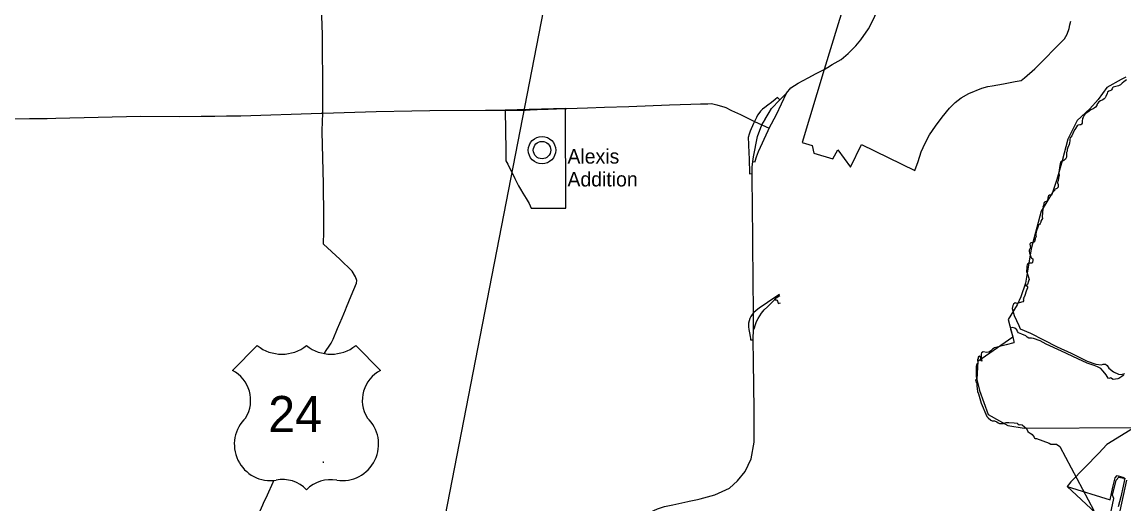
# Model space of a CAD drawing. Extents: x 0 to 750, y 0 to 507.
# Drawn here: x 327.4 to 406.4, y 302.6 to 337.1 of the extents above; entities that cross this region are included whole.
import ezdxf

# ---------------------------------------------------------------- set-up
doc = ezdxf.new("R2010")
doc.units = 0
for name, color, linetype in [('DV_X_Corp_Line', 7, 'Continuous'), ('GM_X_County', 7, 'Continuous'), ('GM_X_Interchange_Ramps', 7, 'Continuous'), ('GM_X_Interstate_Route', 7, 'Continuous'), ('GM_X_Rail_Line', 7, 'Continuous'), ('GM_X_State_Route', 7, 'Continuous'), ('GM_X_US_Route', 7, 'Continuous'), ('SH_Data', 7, 'Continuous')]:
    doc.layers.add(name, color=color, linetype=linetype)

msp = doc.modelspace()

# ---------------------------------------------------------------- linework, layer by layer
at = {"layer": 'DV_X_Corp_Line'}
for points in [[(386.603, 339.237), (385.928, 336.978), (384.925, 333.716), (383.344, 328.467), (384.054, 328.263), (384.187, 327.707), (385.543, 327.316), (385.894, 327.945), (386.801, 326.717), (387.606, 328.321), (391.432, 326.469), (391.659, 327.121), (391.872, 327.808), (392.162, 328.419), (392.468, 329.014), (392.894, 329.657), (393.381, 330.299), (393.907, 330.931), (394.304, 331.334), (394.75, 331.676), (395.285, 331.982), (396.216, 332.36), (396.668, 332.496), (396.964, 332.546), (397.77, 332.676), (398.618, 332.851), (399.058, 332.907), (399.277, 333.099), (400.018, 333.756), (402.156, 335.914), (402.357, 336.246), (402.499, 336.649), (402.548, 336.899), (402.608, 337.178)], [(406.565, 333.158), (406.225, 332.985), (405.184, 332.415), (404.569, 331.568), (403.968, 330.884), (403.068, 330.053), (402.407, 328.725), (401.978, 327.164), (401.6, 325.819), (401.287, 324.901), (400.49, 323.558), (399.763, 320.859), (399.594, 319.836), (399.361, 318.388), (399.022, 317.425), (398.755, 316.846), (398.12, 315.8), (398.447, 314.534), (395.94, 312.788), (395.871, 311.487), (396.061, 310.702), (396.672, 308.99), (398.093, 308.182), (399.258, 308.013), (407.183, 308.053), (405.205, 306.834), (404.62, 306.208), (402.601, 304.165), (402.358, 303.814), (404.38, 301.943)], [(404.38, 301.943), (402.358, 303.814), (405.428, 302.869), (405.623, 303.771), (405.781, 304.437), (405.942, 304.621), (406.416, 304.472), (406.456, 304.307), (406.368, 303.846), (406.189, 303.085), (406.015, 302.368)]]:
    msp.add_lwpolyline(points, dxfattribs=at)
msp.add_lwpolyline([(362.075, 327.909), (362.085, 327.165), (362.22, 326.918), (362.346, 326.651), (362.55, 326.243), (362.719, 325.892), (362.874, 325.597), (362.993, 325.365), (363.134, 325.14), (363.31, 324.852), (363.542, 324.459), (363.753, 324.107), (363.906, 323.769), (366.389, 323.764), (366.35, 330.91), (362.041, 330.785)], close=True, dxfattribs=at)
for radius in [0.982, 0.623]:
    msp.add_circle((364.676, 327.927), radius, dxfattribs=at)
at = {"layer": 'GM_X_County'}
for points in [[(406.615, 332.959), (406.409, 332.826), (406.293, 332.731), (406.167, 332.601), (406.035, 332.529), (405.738, 332.457), (405.65, 332.437), (405.608, 332.402), (405.583, 332.323), (405.534, 332.251), (405.478, 332.212), (405.348, 332.156), (405.253, 332.072), (405.214, 331.98), (405.128, 331.764), (405.07, 331.678), (405.003, 331.601), (404.917, 331.536), (404.745, 331.471), (404.615, 331.383), (404.539, 331.3), (404.483, 331.191), (404.465, 331.121), (404.383, 331.001), (404.288, 330.931), (404.214, 330.898), (404.045, 330.808), (403.827, 330.639), (403.646, 330.518), (403.546, 330.4), (403.514, 330.319), (403.493, 330.268), (403.46, 330.193), (403.435, 330.015), (403.418, 329.933), (403.425, 329.859), (403.388, 329.785), (403.349, 329.75), (403.256, 329.734), (403.126, 329.711), (403.07, 329.662), (402.892, 329.395), (402.804, 329.249), (402.753, 329.115), (402.676, 328.948), (402.56, 328.801), (402.532, 328.713), (402.53, 328.588), (402.523, 328.46), (402.481, 328.323), (402.4, 328.124), (402.342, 327.976), (402.344, 327.853), (402.312, 327.769), (402.305, 327.523), (402.289, 327.416), (402.233, 327.282), (402.119, 327.177), (402.006, 327.126), (401.911, 327.106), (401.863, 327.062), (401.841, 326.945), (401.808, 326.681), (401.774, 326.479), (401.746, 326.384), (401.739, 326.296), (401.769, 326.11), (401.725, 325.925), (401.699, 325.723), (401.66, 325.644), (401.651, 325.574), (401.692, 325.456), (401.713, 325.349), (401.695, 325.268), (401.611, 325.173), (401.556, 325.15), (401.479, 325.131), (401.472, 325.101), (401.484, 325.085), (401.414, 325.022), (401.312, 324.923), (401.261, 324.825), (401.245, 324.749), (401.219, 324.702), (401.191, 324.695), (401.129, 324.705), (401.089, 324.7), (401.02, 324.656), (400.992, 324.596), (400.932, 324.34), (400.876, 324.238), (400.825, 324.215), (400.76, 324.222), (400.718, 324.208), (400.702, 324.178), (400.674, 324.092), (400.646, 323.937), (400.63, 323.913), (400.609, 323.883), (400.623, 323.835), (400.628, 323.753), (400.604, 323.688), (400.588, 323.461), (400.553, 323.155), (400.581, 323.034), (400.539, 322.953), (400.465, 322.837), (400.451, 322.761), (400.403, 322.665), (400.361, 322.607), (400.328, 322.603), (400.294, 322.559), (400.243, 322.413), (400.157, 322.155), (400.134, 322.065), (400.131, 322.018), (400.092, 321.923), (400.101, 321.863), (400.106, 321.798), (400.122, 321.705), (400.099, 321.668), (400.062, 321.617), (400.041, 321.545), (400.038, 321.468), (399.997, 321.355), (399.92, 321.306), (399.832, 321.29), (399.737, 321.28), (399.707, 321.269), (399.688, 321.243), (399.681, 321.185), (399.69, 321.065), (399.723, 320.956), (399.672, 320.844), (399.621, 320.752), (399.619, 320.668), (399.649, 320.566), (399.697, 320.423), (399.772, 320.202), (399.823, 320.188), (399.876, 320.127), (399.883, 320.051), (399.853, 319.886), (399.823, 319.835), (399.667, 319.817), (399.63, 319.824), (399.579, 319.828), (399.54, 319.807), (399.496, 319.775), (399.498, 319.74), (399.503, 319.722), (399.477, 319.698), (399.456, 319.617), (399.456, 319.52), (399.435, 319.22), (399.482, 319.104), (399.57, 318.814), (399.621, 318.647), (399.567, 318.529), (399.491, 318.29), (399.465, 318.262), (399.426, 318.253), (399.387, 318.251), (399.377, 318.23), (399.389, 318.209), (399.412, 318.204), (399.47, 318.179), (399.493, 318.149), (399.498, 318.07), (399.414, 317.819), (399.301, 317.499), (399.245, 317.337), (399.196, 317.267), (399.206, 317.223), (399.208, 317.184), (399.208, 317.123), (399.157, 317.047), (398.901, 316.99), (398.769, 316.935), (398.609, 316.978), (398.502, 316.894), (398.451, 316.802), (398.407, 316.568), (398.543, 316.082), (398.879, 315.361), (398.982, 315.119), (399.708, 314.808), (400.66, 314.331), (401.623, 313.832), (402.634, 313.375), (403.793, 312.815), (404.41, 312.585), (404.806, 312.551), (404.927, 312.595), (405.092, 312.588), (405.227, 312.482), (405.333, 312.295), (405.67, 312.039), (406.021, 311.882), (406.211, 311.849), (406.321, 311.863), (406.487, 311.908)], [(406.423, 311.808), (406.2, 311.669), (406.057, 311.571), (405.984, 311.534), (405.655, 311.483), (405.589, 311.519), (405.516, 311.596), (405.439, 311.607), (405.399, 311.578), (405.344, 311.563), (405.289, 311.593), (405.146, 311.816), (404.927, 312.079), (404.755, 312.284), (404.521, 312.39), (404.287, 312.485), (403.774, 312.672), (403.116, 312.961), (401.941, 313.513), (400.84, 314.029), (400.416, 314.252), (399.944, 314.432), (399.783, 314.45), (399.596, 314.443), (399.487, 314.523), (399.373, 314.611), (399.095, 314.75), (398.861, 314.845), (398.777, 314.936), (398.733, 315.061), (398.601, 315.167), (398.411, 315.226), (398.287, 315.167), (398.283, 315.097), (398.367, 314.797), (398.422, 314.64), (398.532, 314.212), (398.524, 314.117), (397.983, 313.967), (397.14, 313.754), (397.127, 313.753), (396.992, 313.664), (396.882, 313.554), (396.732, 313.458), (396.588, 313.434), (396.333, 313.469), (396.198, 313.396), (396.187, 313.308), (396.187, 313.093), (396.205, 312.957), (396.223, 312.8), (396.187, 312.826), (396.146, 312.983), (396.106, 313.129), (396.066, 313.188), (396.048, 313.173), (395.963, 313.1), (395.956, 313.005), (395.916, 312.928), (395.916, 312.822), (395.934, 312.73), (395.916, 312.613), (395.85, 312.573), (395.824, 312.397), (395.821, 311.695), (395.854, 311.636), (395.872, 311.56), (395.832, 311.497), (395.784, 311.439), (395.795, 311.38), (395.821, 311.263), (395.868, 311.223), (395.857, 311.033), (395.916, 310.641), (395.978, 310.455), (396.179, 309.8), (396.578, 308.845), (396.67, 308.739), (396.867, 308.585), (396.973, 308.534), (397.068, 308.534), (397.145, 308.523), (397.295, 308.454), (397.405, 308.384), (397.485, 308.344), (397.591, 308.336), (397.782, 308.336), (397.837, 308.351), (397.972, 308.41), (398.17, 308.399), (398.554, 308.395), (398.751, 308.355), (398.813, 308.304), (398.905, 308.249), (399.015, 308.263), (399.128, 308.234), (399.282, 308.088), (399.424, 307.967), (399.52, 307.755), (399.655, 307.663), (399.746, 307.612), (399.845, 307.546), (399.977, 307.352), (400.013, 307.286), (400.061, 307.257), (400.149, 307.268), (401.056, 306.928), (401.184, 306.866), (401.455, 306.866), (401.572, 306.847), (401.817, 306.686), (404.25, 302.102)], [(405.311, 301.169), (405.684, 302.955), (405.589, 303.196), (405.86, 304.279), (406.043, 304.499), (406.526, 304.389)], [(406.599, 304.279), (406.006, 301.535), (406.123, 301.36), (406.474, 301.286)]]:
    msp.add_lwpolyline(points, dxfattribs=at)
at = {"layer": 'GM_X_Interchange_Ramps'}
for points in [[(381.736, 331.53), (381.559, 331.704), (381.392, 331.568), (381.141, 331.353), (380.874, 331.151), (380.652, 330.988), (380.484, 330.856), (380.34, 330.712), (380.221, 330.565), (380.141, 330.425), (380.056, 330.257), (379.944, 330.03), (379.925, 329.991)], [(379.925, 329.991), (379.854, 329.845), (379.601, 329.297), (379.526, 329.065), (379.474, 328.834), (379.474, 328.664), (379.478, 328.516), (379.477, 328.325), (379.511, 327.708), (379.529, 327.321), (379.569, 326.239), (379.747, 326.242)], [(379.798, 327.121), (379.957, 327.099), (379.964, 327.129), (380.064, 327.437), (380.213, 327.836), (380.9, 329.344), (380.971, 329.503)], [(381.708, 317.583), (381.455, 317.411), (380.258, 316.614), (380.047, 316.434), (379.857, 316.265), (379.748, 316.139), (379.656, 316.007), (379.579, 315.859), (379.526, 315.695), (379.496, 315.539), (379.483, 315.41), (379.484, 315.269), (379.517, 315.064), (379.56, 314.832), (379.604, 314.561), (379.633, 314.419), (379.639, 314.341), (379.833, 314.339)], [(379.843, 315.119), (379.89, 315.118), (379.908, 315.193), (379.957, 315.361), (380.067, 315.638), (380.18, 315.867), (380.293, 316.058), (380.425, 316.24), (380.613, 316.473), (380.844, 316.709), (381.19, 317.029), (381.317, 317.16), (381.373, 317.219), (381.484, 317.335), (381.727, 317.501)], [(381.373, 317.219), (381.393, 317.203), (381.436, 317.209), (381.482, 317.203), (381.517, 317.181), (381.569, 317.095), (381.594, 317.036), (381.61, 316.967), (381.61, 316.943), (381.781, 316.981)]]:
    msp.add_lwpolyline(points, dxfattribs=at)
at = {"layer": 'GM_X_Interstate_Route'}
for p, q in [((344.248, 313.917), (342.471, 312.14)), ((344.248, 313.917), (342.471, 312.14)), ((353.089, 312.14), (351.312, 313.917)), ((353.089, 312.14), (351.312, 313.917))]:
    msp.add_line(p, q, dxfattribs=at)
for points in [[(385.15, 333.851), (385.501, 334.07), (386.126, 334.433), (386.646, 334.843), (387.194, 335.398), (387.554, 335.844), (388.099, 336.625), (388.504, 337.402), (388.71, 337.946), (388.832, 338.536), (389.981, 342.748)], [(382.221, 332.02), (382.523, 332.402), (383.058, 332.716), (383.758, 333.103), (384.332, 333.412), (384.925, 333.716), (385.107, 333.824), (385.15, 333.851)], [(380.683, 330.142), (380.966, 330.615), (381.134, 330.909), (381.736, 331.53), (382.221, 332.02)], [(379.849, 312.749), (379.833, 314.339), (379.843, 315.119), (379.857, 316.228), (379.857, 316.265), (379.803, 321.141), (379.798, 321.9), (379.786, 323.571), (379.747, 326.242), (379.74, 326.7), (379.798, 327.121), (379.844, 327.453), (380.136, 328.898), (380.443, 329.74)], [(380.443, 329.74), (380.675, 330.129), (380.683, 330.142)], [(375.239, 302.766), (375.832, 302.897), (376.023, 302.939), (377.074, 303.235), (378.118, 303.713), (378.711, 304.236), (379.25, 304.885), (379.688, 305.796), (379.894, 307.007), (379.884, 309.328), (379.849, 312.749)], [(372.088, 301.799), (372.436, 301.978), (372.959, 302.218), (373.469, 302.386), (374.053, 302.513), (375.127, 302.741), (375.239, 302.766)]]:
    msp.add_lwpolyline(points, dxfattribs=at)
for centre, radius, start, end in [((346.014, 316.162), 2.856, 231.81301, 308.18697), ((346.014, 316.162), 2.856, 231.81301, 308.18697), ((349.546, 316.162), 2.856, 231.81301, 308.18697), ((349.546, 316.162), 2.856, 231.81301, 308.18697), ((341.36, 309.995), 2.416, 329.11751, 62.61081), ((341.36, 309.995), 2.416, 329.11751, 62.61081), ((354.2, 309.995), 2.416, 117.38919, 210.88249), ((354.2, 309.995), 2.416, 117.38919, 210.88249), ((345.211, 306.848), 2.607, 133.00455, 278.72816), ((345.211, 306.848), 2.607, 133.00455, 278.72816), ((350.349, 306.848), 2.607, 261.27184, 46.99545), ((350.349, 306.848), 2.607, 261.27184, 46.99545), ((346.086, 301.99), 2.332, 43.41772, 101.87423), ((346.086, 301.99), 2.332, 43.41772, 101.87423), ((349.522, 301.835), 2.475, 79.96126, 134.74679), ((349.522, 301.835), 2.475, 79.96126, 134.74679)]:
    msp.add_arc(centre, radius, start, end, dxfattribs=at)
at = {"layer": 'GM_X_Rail_Line'}
for points in [[(348.943, 305.566), (349.033, 305.569)], [(349.006, 305.558), (348.943, 305.566)]]:
    msp.add_lwpolyline(points, dxfattribs=at)
at = {"layer": 'GM_X_State_Route'}
for points in [[(380.971, 329.503), (381.487, 330.484), (382.221, 332.02)], [(369.152, 331.001), (370.903, 331.066), (373.824, 331.176), (375.341, 331.226), (376.038, 331.249), (376.561, 331.253), (376.843, 331.265), (377.209, 331.181), (377.799, 330.999), (377.857, 330.972)], [(335.873, 330.372), (338.668, 330.337), (340.217, 330.358), (341.204, 330.372), (342.046, 330.383), (342.498, 330.39), (343.074, 330.397), (348.824, 330.581)], [(348.824, 330.581), (348.955, 330.585), (352.782, 330.704), (355.336, 330.741), (356.641, 330.779)], [(356.641, 330.779), (360.63, 330.784)], [(360.63, 330.784), (362.045, 330.785)], [(362.045, 330.785), (363.495, 330.795), (364.189, 330.842)], [(364.189, 330.842), (364.33, 330.851), (365.126, 330.874)], [(365.126, 330.874), (366.332, 330.909)], [(366.332, 330.909), (366.468, 330.913), (367.94, 330.955), (369.152, 331.001)], [(377.857, 330.972), (378.224, 330.802)], [(378.224, 330.802), (378.274, 330.779), (378.907, 330.485), (379.925, 329.991), (380.443, 329.74)], [(320.598, 330.15), (320.658, 330.15), (321.814, 330.134), (322.842, 330.12), (323.926, 330.135), (325.804, 330.16), (327.917, 330.189), (328.693, 330.2)], [(328.693, 330.2), (329.184, 330.206), (329.79, 330.215), (335.873, 330.372)], [(380.443, 329.74), (380.971, 329.503)]]:
    msp.add_lwpolyline(points, dxfattribs=at)
at = {"layer": 'GM_X_US_Route'}
for points in [[(348.931, 336.2), (348.717, 342.287)], [(348.956, 331.107), (348.957, 331.883), (348.932, 336.181), (348.931, 336.2)], [(348.901, 329.343), (348.955, 330.585)], [(348.955, 330.585), (348.955, 331.021), (348.956, 331.107)], [(349.025, 322.158), (349.031, 322.515), (349.031, 322.533), (349.014, 323.19), (349.014, 323.256), (349.016, 323.907), (349.016, 323.931), (348.999, 324.718), (348.999, 324.77), (348.997, 325.461), (348.995, 325.522), (348.896, 329.24), (348.901, 329.343)], [(351.301, 318.843), (351.063, 319.264), (350.169, 320.123), (349.01, 321.191), (349.024, 322.101), (349.025, 322.158)], [(351.371, 318.391), (351.384, 318.574), (351.301, 318.843)], [(350.581, 316.477), (350.663, 316.672), (350.992, 317.483), (351.371, 318.391)], [(349.063, 313.367), (349.231, 313.63), (349.357, 313.81), (349.548, 314.086), (349.696, 314.383), (350.017, 315.14), (350.342, 315.913), (350.581, 316.477)], [(344.281, 301.69), (344.282, 301.691), (344.291, 301.713), (344.339, 301.819), (344.65, 302.506), (344.701, 302.618), (344.973, 303.218), (345.388, 304.136), (345.437, 304.256)]]:
    msp.add_lwpolyline(points, dxfattribs=at)
at = {"layer": 'SH_Data'}
msp.add_line((365.785, 343.117), (357.52, 300.669), dxfattribs=at)

# ---------------------------------------------------------------- texts
at = {"layer": 'DV_X_Corp_Line'}
for s, p in [('Alexis', (366.503, 326.962)), ('Addition', (366.503, 325.323))]:
    msp.add_text(s, height=1.0417, rotation=0.00001, dxfattribs=at).set_placement(p)
at = {"layer": 'GM_X_Interstate_Route'}
msp.add_text('24', height=2.5875, dxfattribs=at).set_placement((345.039, 307.721))

doc.saveas('drawing.dxf')
